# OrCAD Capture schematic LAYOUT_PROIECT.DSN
size A
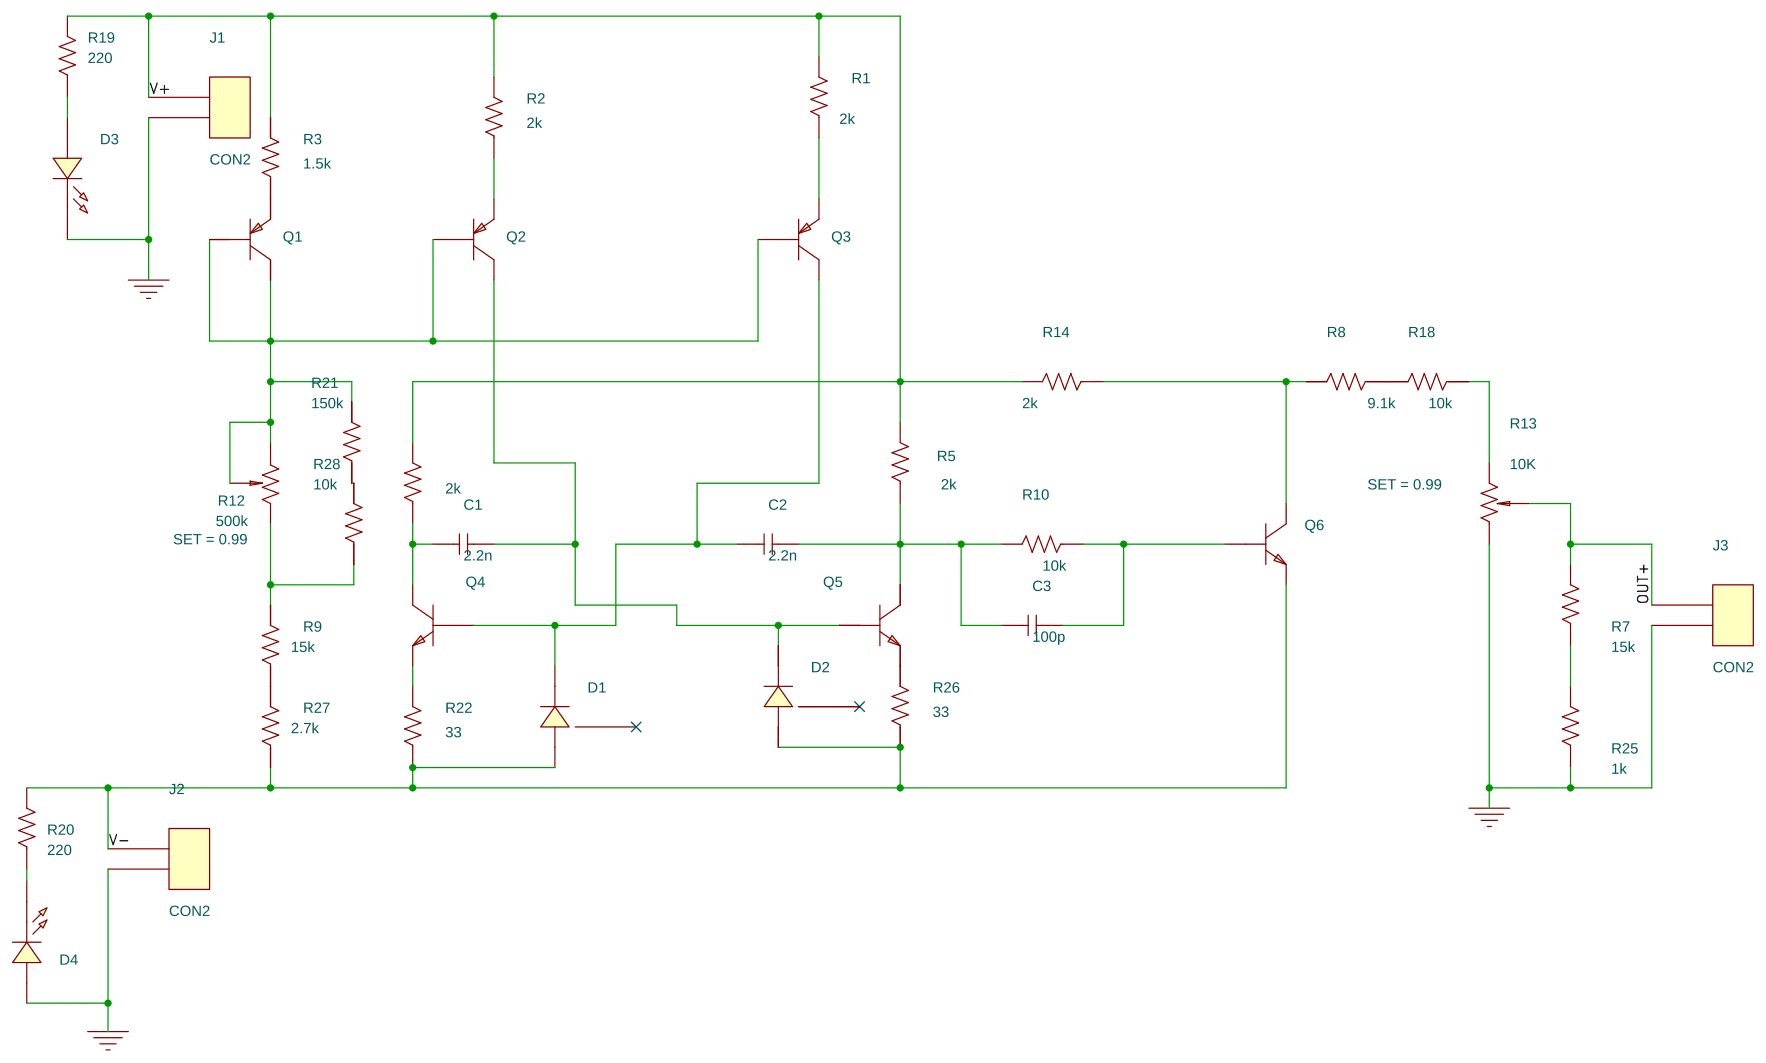
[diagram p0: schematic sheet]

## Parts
C1  2.2n  [SMC0805]
C2  2.2n  [SMC0805]
C3  100p  [SMC0805]
D1  BZX84-C5V6  [TO236AA]
D2  BZX84-C5V6  [TO236AA]
D3  5V,LED,LED  [SMD0805]
D4  5V,LED,LED  [SMD0805]
J1  CON2  [SMR2512]
J2  CON2  [SMR2512]
J3  CON2  [SMR2512]
Q1  QBC856B  [TO236AA]
Q2  QBC856B  [TO236AA]
Q3  QBC856B  [TO236AA]
Q4  QBC846B  [TO236AA]
Q5  QBC846B  [TO236AA]
Q6  QBC846B  [TO236AA]
R1  2k  [SMR0805]
R2  2k  [SMR0805]
R3  1.5k  [SMR0805]
R4  2k  [SMR0805]
R5  2k  [SMR0805]
R7  15k  [SMR0805]
R8  9.1k  [SMR0805]
R9  15k  [SMR0805]
R10  10k  [SMR0805]
R12  500k  [TS53YL]
R13  10K  [TS53YL]
R14  2k  [SMR0805]
R18  10k  [SMR0805]
R19  220  [SMR0805]
R20  220  [SMR0805]
R21  150k  [SMR0805]
R22  33  [SMR0805]
R25  1k  [SMR0805]
R26  33  [SMR0805]
R27  2.7k  [SMR0805]
R28  10k  [SMR0805]

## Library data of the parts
C1-C3 = C
D1 D2 = BZX84-C5V6_9
D3 D4 = LED_5: AppProp: mN=LED,fV=3,fC=30E-3; BV: 5; IBV: 10e-6; IF: 160E-3; IS: 2.6404e-027; PDM: 114E-3; RS: 2; VR: 5
J1-J3 = CON2
Q1-Q3 = QBC856B_0
Q4-Q6 = QBC846B_0
R1-R5 R7-R10 R14 R18-R22 R25-R28 = R
R12 R13 = POT_0: SET: 0.99

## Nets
GND: D3.C D4.A J1.2 J2.2 J3.2 R13.1(CCW) R25.1
OUT+: J3.1 R7.2 R13.2(WIPER)
V+: J1.1 R1.2 R2.2 R3.2 R4.2 R5.2 R14.2 R19.2
V-: D1.1(A) D2.1(A) J2.1 Q6.2(E) R20.2 R22.1 R26.1 R27.1
N103383: D3.A R19.1
N103451: Q3.2(E) R1.1
N103463: Q2.2(E) R2.1
N103557: Q1.1(B) Q1.3(C) Q2.1(B) Q3.1(B) R12.1(CCW) R12.2(WIPER) R21.2
N103581: C1.2 D2.3(C) Q2.3(C) Q5.1(B)
N103587: C2.1 D1.3(C) Q3.3(C) Q4.1(B)
N103701: Q6.3(C) R8.2 R14.1
N103715: R13.3(CW) R18.1
N103835: R21.1 R28.2
N103897: C2.2 C3.1 Q5.3(C) R5.1 R10.2
N103911: R9.2 R12.3(CW) R28.1
N103917: C1.1 Q4.3(C) R4.1
N104055: C3.2 Q6.1(B) R10.1
N104249: R7.1 R25.2
N104493: D4.C R20.1
N105640: Q4.2(E) R22.2
N112087: Q1.2(E) R3.1
N112088: Q5.2(E) R26.2
N112089: R8.1 R18.2
N112090: R9.1 R27.2

Not connected (* = marked no-connect by the designer): D1 2*; D2 2*
